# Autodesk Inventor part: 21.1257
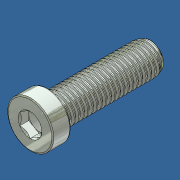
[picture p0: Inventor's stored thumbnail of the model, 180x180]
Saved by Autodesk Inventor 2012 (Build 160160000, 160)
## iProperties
Created: 2010-11
Part Number: 21.1257
Document SubType Name: Modeling
Designer: Administrator
Density: 7.85 g/cm^3
Material: Steel
Mass: 43.046 g
Surface Area: 30.654 cm^2
Volume: 5.48356 cm^3
Description: M12x40 SHCS Zinc Plated
Vendor: S
Translation Standard: STEP AP203
FileName: 93070A249.step
PreProcessor: SolidWorks 2003314
PostProcessor: Build: 236a, Release: 2009 RTM - Date: Fri 02/22/2008
Sent Units: MM
Uncertainty: 1e-05
Title: M12x40 SHCS Zinc Plated
Author: Administrator
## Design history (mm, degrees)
feature "Base1"
body "Solid1"
